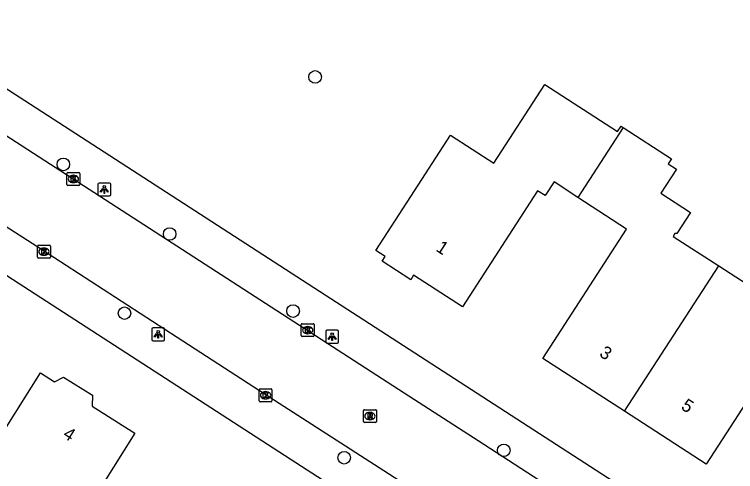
# Model space of a CAD drawing. Extents: x 161141 to 161601, y 381708 to 382245.
# Drawn here: x 161326.4 to 161382.4, y 382046.4 to 382081.9 of the extents above; entities that cross this region are included whole.
import ezdxf

# ---------------------------------------------------------------- set-up
doc = ezdxf.new("R2010")
doc.units = 0
for name, color, linetype in [('IMGEO_Boom', 7, 'Continuous'), ('IMGEO_Kolk', 7, 'Continuous'), ('IMGEO_Lichtpunt', 7, 'Continuous'), ('IMGEO_Pand', 7, 'Continuous'), ('IMGEO_Pand_nummerreeks', 7, 'Continuous'), ('IMGEO_Rijbaan_lokaal_open', 7, 'Continuous'), ('IMGEO_Rioolput', 7, 'Continuous'), ('IMGEO_Voetpad_open', 7, 'Continuous')]:
    doc.layers.add(name, color=color, linetype=linetype)

msp = doc.modelspace()

# ---------------------------------------------------------------- linework, layer by layer
at = {"layer": 'IMGEO_Boom'}
for centre in [(161349.751, 382077.022), (161330.202, 382070.239), (161338.459, 382064.833), (161334.95, 382058.691), (161348.037, 382058.854), (161364.4, 382048.05), (161352.004, 382047.471)]:
    msp.add_circle(centre, 0.489, dxfattribs=at)
at = {"layer": 'IMGEO_Kolk'}
for p, q in [((161330.485, 382068.685), (161330.485, 382069.537)), ((161330.56, 382069.611), (161331.412, 382069.611)), ((161331.486, 382069.537), (161331.486, 382068.685)), ((161330.973, 382069.391), (161330.998, 382069.391)), ((161331.412, 382068.611), (161330.56, 382068.611)), ((161330.996, 382068.831), (161330.971, 382068.831)), ((161328.273, 382063.968), (161329.125, 382063.968)), ((161328.198, 382063.042), (161328.198, 382063.894)), ((161328.686, 382063.748), (161328.711, 382063.748)), ((161329.199, 382063.894), (161329.199, 382063.042)), ((161329.125, 382062.968), (161328.273, 382062.968)), ((161328.709, 382063.188), (161328.684, 382063.188)), ((161348.679, 382056.948), (161348.679, 382057.8)), ((161348.754, 382057.874), (161349.606, 382057.874)), ((161349.68, 382057.8), (161349.68, 382056.948)), ((161349.167, 382057.654), (161349.192, 382057.654)), ((161349.606, 382056.874), (161348.754, 382056.874)), ((161349.19, 382057.094), (161349.165, 382057.094)), ((161345.399, 382051.898), (161345.399, 382052.75)), ((161345.474, 382052.824), (161346.326, 382052.824)), ((161346.4, 382052.75), (161346.4, 382051.898)), ((161345.887, 382052.604), (161345.912, 382052.604)), ((161346.326, 382051.824), (161345.474, 382051.824)), ((161345.91, 382052.044), (161345.885, 382052.044))]:
    msp.add_line(p, q, dxfattribs=at)
for points in [[(161330.485, 382068.685), (161330.485, 382069.537)], [(161330.56, 382069.611), (161331.412, 382069.611)], [(161331.486, 382069.537), (161331.486, 382068.685)], [(161330.806, 382069.311), (161330.929, 382069.311), (161330.929, 382069.16), (161331.059, 382069.311), (161331.223, 382069.311), (161331.077, 382069.16), (161331.23, 382068.911), (161331.078, 382068.911), (161330.993, 382069.075), (161330.929, 382069.008), (161330.929, 382068.911), (161330.806, 382068.911), (161330.806, 382069.311)], [(161331.412, 382068.611), (161330.56, 382068.611)], [(161328.273, 382063.968), (161329.125, 382063.968)], [(161328.198, 382063.042), (161328.198, 382063.894)], [(161328.519, 382063.668), (161328.642, 382063.668), (161328.642, 382063.517), (161328.772, 382063.668), (161328.936, 382063.668), (161328.79, 382063.517), (161328.943, 382063.268), (161328.791, 382063.268), (161328.706, 382063.432), (161328.642, 382063.365), (161328.642, 382063.268), (161328.519, 382063.268), (161328.519, 382063.668)], [(161329.199, 382063.894), (161329.199, 382063.042)], [(161329.125, 382062.968), (161328.273, 382062.968)], [(161348.679, 382056.948), (161348.679, 382057.8)], [(161348.754, 382057.874), (161349.606, 382057.874)], [(161349.68, 382057.8), (161349.68, 382056.948)], [(161349, 382057.574), (161349.123, 382057.574), (161349.123, 382057.423), (161349.253, 382057.574), (161349.417, 382057.574), (161349.271, 382057.423), (161349.424, 382057.174), (161349.272, 382057.174), (161349.187, 382057.338), (161349.123, 382057.271), (161349.123, 382057.174), (161349, 382057.174), (161349, 382057.574)], [(161349.606, 382056.874), (161348.754, 382056.874)], [(161345.399, 382051.898), (161345.399, 382052.75)], [(161345.474, 382052.824), (161346.326, 382052.824)], [(161346.4, 382052.75), (161346.4, 382051.898)], [(161345.72, 382052.524), (161345.843, 382052.524), (161345.843, 382052.373), (161345.973, 382052.524), (161346.137, 382052.524), (161345.991, 382052.373), (161346.144, 382052.124), (161345.992, 382052.124), (161345.907, 382052.288), (161345.843, 382052.221), (161345.843, 382052.124), (161345.72, 382052.124), (161345.72, 382052.524)], [(161346.326, 382051.824), (161345.474, 382051.824)]]:
    msp.add_lwpolyline(points, dxfattribs=at)
for centre, start, end in [((161330.562, 382069.535), 91.552, 178.448), ((161330.562, 382069.535), 91.552, 178.448), ((161331.41, 382069.535), 1.552, 88.448), ((161331.41, 382069.535), 1.552, 88.448), ((161330.562, 382068.687), 181.552, 268.448), ((161330.562, 382068.687), 181.552, 268.448), ((161331.41, 382068.687), 271.552, 358.448), ((161331.41, 382068.687), 271.552, 358.448), ((161328.275, 382063.892), 91.552, 178.448), ((161328.275, 382063.892), 91.552, 178.448), ((161329.123, 382063.892), 1.552, 88.448), ((161329.123, 382063.892), 1.552, 88.448), ((161328.275, 382063.044), 181.552, 268.448), ((161328.275, 382063.044), 181.552, 268.448), ((161329.123, 382063.044), 271.552, 358.448), ((161329.123, 382063.044), 271.552, 358.448), ((161348.756, 382057.798), 91.552, 178.448), ((161348.756, 382057.798), 91.552, 178.448), ((161349.604, 382057.798), 1.552, 88.448), ((161349.604, 382057.798), 1.552, 88.448), ((161348.756, 382056.95), 181.552, 268.448), ((161348.756, 382056.95), 181.552, 268.448), ((161349.604, 382056.95), 271.552, 358.448), ((161349.604, 382056.95), 271.552, 358.448), ((161345.476, 382052.748), 91.552, 178.448), ((161345.476, 382052.748), 91.552, 178.448), ((161346.324, 382052.748), 1.552, 88.448), ((161346.324, 382052.748), 1.552, 88.448), ((161345.476, 382051.9), 181.552, 268.448), ((161345.476, 382051.9), 181.552, 268.448), ((161346.324, 382051.9), 271.552, 358.448), ((161346.324, 382051.9), 271.552, 358.448)]:
    msp.add_arc(centre, 0.0765, start, end, dxfattribs=at)
for centre, major_axis, ratio, start_param, end_param in [((161330.972, 382069.111), (-0.387, 0.002), 0.722429, 4.712389, 7.853982), ((161330.997, 382069.111), (-0.39, 0.002), 0.717154, 1.570796, 4.712389), ((161328.685, 382063.468), (-0.387, 0.002), 0.722429, 4.712389, 7.853982), ((161328.71, 382063.468), (-0.39, 0.002), 0.717154, 1.570796, 4.712389), ((161349.166, 382057.374), (-0.387, 0.002), 0.722429, 4.712389, 7.853982), ((161349.191, 382057.374), (-0.39, 0.002), 0.717154, 1.570796, 4.712389), ((161345.886, 382052.324), (-0.387, 0.002), 0.722429, 4.712389, 7.853982), ((161345.911, 382052.324), (-0.39, 0.002), 0.717154, 1.570796, 4.712389)]:
    msp.add_ellipse(centre, major_axis=major_axis, ratio=ratio, start_param=start_param, end_param=end_param, dxfattribs=at)
at = {"layer": 'IMGEO_Lichtpunt'}
for p, q in [((161332.883, 382068.696), (161332.883, 382067.889)), ((161332.883, 382068.696), (161332.883, 382067.889)), ((161333.785, 382068.791), (161332.977, 382068.791)), ((161333.785, 382068.791), (161332.977, 382068.791)), ((161333.879, 382067.889), (161333.879, 382068.696)), ((161333.879, 382067.889), (161333.879, 382068.696)), ((161332.977, 382067.795), (161333.785, 382067.795)), ((161332.977, 382067.795), (161333.785, 382067.795)), ((161337.071, 382057.45), (161337.071, 382056.643)), ((161337.071, 382057.45), (161337.071, 382056.643)), ((161337.973, 382057.545), (161337.165, 382057.545)), ((161337.973, 382057.545), (161337.165, 382057.545)), ((161338.067, 382056.643), (161338.067, 382057.45)), ((161338.067, 382056.643), (161338.067, 382057.45)), ((161350.574, 382057.276), (161350.574, 382056.469)), ((161350.574, 382057.276), (161350.574, 382056.469)), ((161351.476, 382057.371), (161350.668, 382057.371)), ((161351.476, 382057.371), (161350.668, 382057.371)), ((161351.57, 382056.469), (161351.57, 382057.276)), ((161351.57, 382056.469), (161351.57, 382057.276)), ((161337.165, 382056.549), (161337.973, 382056.549)), ((161337.165, 382056.549), (161337.973, 382056.549)), ((161350.668, 382056.375), (161351.476, 382056.375)), ((161350.668, 382056.375), (161351.476, 382056.375))]:
    msp.add_line(p, q, dxfattribs=at)
for points in [[(161333.257, 382068.36), (161333.296, 382068.332), (161333.108, 382068.07), (161333.07, 382068.097), (161333.257, 382068.36)], [(161333.359, 382068.312), (161333.406, 382068.312), (161333.406, 382067.99), (161333.359, 382067.99), (161333.359, 382068.312)], [(161333.469, 382068.332), (161333.507, 382068.359), (161333.694, 382068.097), (161333.655, 382068.069), (161333.469, 382068.332)], [(161337.445, 382057.114), (161337.484, 382057.086), (161337.296, 382056.824), (161337.258, 382056.851), (161337.445, 382057.114)], [(161337.547, 382057.066), (161337.594, 382057.066), (161337.594, 382056.744), (161337.547, 382056.744), (161337.547, 382057.066)], [(161337.657, 382057.086), (161337.695, 382057.113), (161337.882, 382056.851), (161337.843, 382056.823), (161337.657, 382057.086)], [(161350.948, 382056.94), (161350.987, 382056.912), (161350.799, 382056.65), (161350.761, 382056.677), (161350.948, 382056.94)], [(161351.05, 382056.892), (161351.097, 382056.892), (161351.097, 382056.57), (161351.05, 382056.57), (161351.05, 382056.892)], [(161351.16, 382056.912), (161351.198, 382056.939), (161351.385, 382056.677), (161351.346, 382056.649), (161351.16, 382056.912)]]:
    msp.add_lwpolyline(points, dxfattribs=at)
for centre in [(161333.382, 382068.494), (161337.57, 382057.248), (161351.073, 382057.074)]:
    msp.add_circle(centre, 0.0994, dxfattribs=at)
for centre, start, end in [((161332.977, 382068.696), 90, 180), ((161332.977, 382068.696), 90, 180), ((161333.785, 382068.696), 0, 90), ((161333.785, 382068.696), 0, 90), ((161332.977, 382067.889), 180, 270), ((161332.977, 382067.889), 180, 270), ((161333.785, 382067.889), 270, 0), ((161333.785, 382067.889), 270, 360), ((161337.165, 382057.45), 90, 180), ((161337.165, 382057.45), 90, 180), ((161337.973, 382057.45), 0, 90), ((161337.973, 382057.45), 0, 90), ((161350.668, 382057.276), 90, 180), ((161350.668, 382057.276), 90, 180), ((161351.476, 382057.276), 0, 90), ((161351.476, 382057.276), 0, 90), ((161337.165, 382056.643), 180, 270), ((161337.165, 382056.643), 180, 270), ((161337.973, 382056.643), 270, 0), ((161337.973, 382056.643), 270, 360), ((161350.668, 382056.469), 180, 270), ((161350.668, 382056.469), 180, 270), ((161351.476, 382056.469), 270, 0), ((161351.476, 382056.469), 270, 360)]:
    msp.add_arc(centre, 0.0946, start, end, dxfattribs=at)
at = {"layer": 'IMGEO_Pand'}
for points in [[(161370.156, 382067.673), (161368.301, 382068.878), (161367.614, 382067.814), (161367.026, 382068.194), (161361.193, 382059.186), (161357.399, 382061.642), (161357.171, 382061.289), (161354.949, 382062.728), (161355.18, 382063.085), (161354.467, 382063.546), (161357.185, 382067.744), (161360.263, 382072.498), (161363.625, 382070.32), (161367.586, 382076.436), (161373.234, 382072.779), (161373.506, 382073.199), (161373.678, 382073.088)], [(161373.678, 382073.088), (161370.156, 382067.673)], [(161373.678, 382073.088), (161377.409, 382070.671), (161377.162, 382070.29), (161377.8, 382069.877), (161376.584, 382067.999), (161378.89, 382066.506), (161377.828, 382064.866), (161377.683, 382064.874), (161377.54, 382064.653), (161381.083, 382062.359)], [(161373.783, 382051.081), (161367.441, 382055.187), (161373.936, 382065.217), (161370.156, 382067.673)], [(161381.083, 382062.359), (161384.528, 382060.129), (161385.742, 382062.161), (161387.092, 382064.421), (161390.075, 382062.489), (161393.835, 382060.054)], [(161373.783, 382051.081), (161381.083, 382062.359)], [(161390.289, 382054.594), (161386.608, 382056.985), (161380.125, 382046.974), (161373.783, 382051.081)], [(161327.227, 382031.156), (161324.172, 382033.077), (161327.053, 382037.661), (161320.18, 382041.981), (161322.293, 382045.342), (161322.758, 382045.049), (161325.756, 382049.819), (161328.417, 382054.052), (161329.525, 382053.356), (161330.221, 382053.724), (161332.458, 382052.318), (161332.427, 382051.481), (161335.761, 382049.386), (161329.259, 382039.042), (161331.435, 382037.66)]]:
    msp.add_lwpolyline(points, dxfattribs=at)
at = {"layer": 'IMGEO_Rijbaan_lokaal_open'}
for points in [[(161311.536, 382081.664), (161356.674, 382052.498), (161362.411, 382048.813), (161375.585, 382040.285), (161382.572, 382035.748), (161395.928, 382027.083), (161402.927, 382022.535), (161416.852, 382013.552), (161420.042, 382011.494), (161421.741, 382010.379), (161425.551, 382007.922), (161458.647, 381986.439), (161460.91, 381984.988)], [(161480.897, 381964.849), (161471.977, 381970.646), (161450.889, 381984.377), (161443.856, 381988.93), (161430.314, 381997.713), (161423.318, 382002.239), (161408.287, 382012.005), (161402.555, 382015.697), (161398.439, 382018.395), (161388.068, 382025.069), (161381.679, 382029.228), (161366.307, 382039.161), (161359.944, 382043.32), (161345.442, 382052.667), (161339.032, 382056.795), (161328.504, 382063.628), (161325.321, 382065.668), (161306.338, 382077.878)]]:
    msp.add_lwpolyline(points, dxfattribs=at)
at = {"layer": 'IMGEO_Rioolput'}
for p, q in [((161353.504, 382050.276), (161353.504, 382051.128)), ((161353.579, 382051.202), (161354.431, 382051.202)), ((161354.505, 382051.128), (161354.505, 382050.276)), ((161353.992, 382050.982), (161354.017, 382050.982)), ((161354.431, 382050.202), (161353.579, 382050.202)), ((161354.015, 382050.422), (161353.99, 382050.422))]:
    msp.add_line(p, q, dxfattribs=at)
for points in [[(161353.504, 382050.276), (161353.504, 382051.128)], [(161353.579, 382051.202), (161354.431, 382051.202)], [(161354.505, 382051.128), (161354.505, 382050.276)], [(161354.093, 382050.9), (161353.841, 382050.902), (161353.841, 382050.502)], [(161353.841, 382050.502), (161353.965, 382050.502), (161353.965, 382050.664), (161353.976, 382050.664)], [(161354.019, 382050.821), (161353.965, 382050.821), (161353.965, 382050.74)], [(161353.965, 382050.74), (161354.017, 382050.74)], [(161354.023, 382050.635), (161354.094, 382050.502), (161354.234, 382050.502), (161354.169, 382050.628)], [(161354.431, 382050.202), (161353.579, 382050.202)]]:
    msp.add_lwpolyline(points, dxfattribs=at)
for centre, radius, start, end in [((161353.581, 382051.126), 0.0765, 91.552, 178.448), ((161353.581, 382051.126), 0.0765, 91.552, 178.448), ((161354.429, 382051.126), 0.0765, 1.552, 88.448), ((161354.429, 382051.126), 0.0765, 1.552, 88.448), ((161353.975, 382050.611), 0.0533, 26.0293, 88.6989), ((161354.001, 382050.929), 0.19, 274.7715, 282.9687), ((161354.025, 382050.725), 0.0964, 77.0061, 93.1865), ((161354.039, 382050.782), 0.0378, 276.6634, 79.6772), ((161354.092, 382050.79), 0.109, 350.3612, 89.416), ((161354.09, 382050.79), 0.112, 277.5842, 350.9817), ((161354.074, 382050.575), 0.108, 29.5134, 73.7905), ((161353.581, 382050.278), 0.0765, 181.552, 268.448), ((161353.581, 382050.278), 0.0765, 181.552, 268.448), ((161354.429, 382050.278), 0.0765, 271.552, 358.448), ((161354.429, 382050.278), 0.0765, 271.552, 358.448)]:
    msp.add_arc(centre, radius, start, end, dxfattribs=at)
for centre, major_axis, ratio, start_param, end_param in [((161353.991, 382050.702), (-0.387, 0.002), 0.722429, 4.712389, 7.853982), ((161354.016, 382050.702), (-0.39, 0.002), 0.717154, 1.570796, 4.712389)]:
    msp.add_ellipse(centre, major_axis=major_axis, ratio=ratio, start_param=start_param, end_param=end_param, dxfattribs=at)
at = {"layer": 'IMGEO_Voetpad_open'}
for points in [[(161313.623, 382083.997), (161443.483, 382000), (161462.38, 381987.777)], [(161474.804, 381965.241), (161421.048, 382000), (161306.066, 382074.349)]]:
    msp.add_lwpolyline(points, dxfattribs=at)

# ---------------------------------------------------------------- texts
at = {"layer": 'IMGEO_Pand_nummerreeks'}
for s, rotation, p in [('1', 327.0475, (161359.065, 382063.568)), ('3', 327.0766, (161371.75, 382055.399)), ('5', 327.0778, (161378.092, 382051.292)), ('4', 327.5702, (161330.098, 382049.098))]:
    msp.add_text(s, height=1, rotation=rotation, dxfattribs=at).set_placement(p)

doc.saveas('drawing.dxf')
